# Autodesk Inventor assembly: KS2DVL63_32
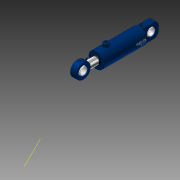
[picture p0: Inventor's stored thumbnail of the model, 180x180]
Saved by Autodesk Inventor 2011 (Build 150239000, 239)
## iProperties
Created: 2010-10
Document SubType Name: Assembly
Designer: TB
Mass: 566.294 g
Surface Area: 1153.75 cm^2
Volume: 566.294 cm^3
Density: 1 g/cm^3
Description: KS2DVL 63/32 - 100 mm
Slaglengde: 100,000 mm
Author: TB
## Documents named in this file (6)
- C:\Vault\Sylinderteknikk\Projects_ST\3D.nettkatalog\KS2-Series\KS2DVL\KS2DVL63_32\KS2DVL63_32.iam
- C:\Vault\Sylinderteknikk\Projects_ST\3D.nettkatalog\KS2-Series\KS2DVL\KS2DVL63_32\KS2DVL63_32_stang.ipt
- C:\Vault\Sylinderteknikk\Projects_ST\3D.nettkatalog\KS2-Series\KS2DVL\KS2DVL63_32\KS2DVL63_32_Parameters.ipt
- C:\Vault\Sylinderteknikk\Projects_ST\3D.nettkatalog\KS2-Series\KS2DVL\KS2DVL63_32\KS2DVL63_32_body..ipt
- C:\Vault\Sylinderteknikk\Projects_ST\Øyer\Klinkby.KS.Øyer\KS.30.eye.komplett\KS30eye.Komplett.ipt
- C:\Vault\Sylinderteknikk\Imported Components\27-7244-03\Part14.ipt
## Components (5 placed, 5 different names)
1. KS2DVL63_32_Parameters:3
2. KS2DVL63_32_stang:1 — Mate:1, FriMate:2, Mate:3, Insert:2
3. KS2DVL63_32_body.:1 — Mate:1, FriMate:2, Mate:3, Angle:1, Insert:3
4. KS30eye.Komplett:1 — Insert:2, Angle:1
5. Part14:1 — Insert:3
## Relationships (6: Mate 3, Insert 2, Angle 1)
- Mate:1: KS2DVL63_32_stang:1 ↔ KS2DVL63_32_body.:1
- FriMate:2 [Mate]: KS2DVL63_32_stang:1 ↔ KS2DVL63_32_body.:1
- Mate:3: KS2DVL63_32_stang:1 ↔ KS2DVL63_32_body.:1
- Insert:2: KS2DVL63_32_stang:1 ↔ KS30eye.Komplett:1
- Angle:1: KS2DVL63_32_body.:1 ↔ KS30eye.Komplett:1
- Insert:3: KS2DVL63_32_body.:1 ↔ Part14:1
## Named parameters: Forlengelse_rør = 0, Vinkel_Minusport = 0
